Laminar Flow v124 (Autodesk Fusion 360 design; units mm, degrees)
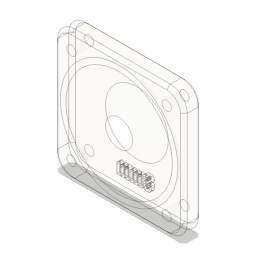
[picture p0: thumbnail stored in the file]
description: Part Number
part number: 73605T67_Brass Garden Hose Fitting
part number: 2706N24_Brass Garden Hose Fitting for Drinking Water
part number: 73605T49_Brass Garden Hose Fitting
named bodies: "Grid", "Backup", "7mm", "8mm", "Backup (1)", "Backup (1) (1)", "allowance", "Backup (1) (1) (1) (1)", "Chamber", "full", "full (1)", "v2-straightener", "inner-cone", "v2-straightener (1)", "grid-v2"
